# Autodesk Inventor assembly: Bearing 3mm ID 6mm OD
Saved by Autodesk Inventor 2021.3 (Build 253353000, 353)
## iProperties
Created: 2022-05
Part Number: Bearing 3mm ID 6mm OD
Document SubType Name: Assembly
Designer: Administrator
Title: Bearing 3mm ID 6mm OD v3
Author: Administrator
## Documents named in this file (2)
- c:\worker\convert-fusion-r03\tmp\job-1\185\output\files\0fa6b6d8-5ae5-4a2f-92c7-634827d88ab4\Bearing 3mm ID 6mm OD v3.iam
- c:\worker\convert-fusion-r03\tmp\job-1\185\output\files\0fa6b6d8-5ae5-4a2f-92c7-634827d88ab4\7487N46_Precision Stainless Steel Ball Bearing.ipt
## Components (1 placed, 1 different names)
1. 7487N46_Precision Stainless Steel Ball Bearing:1
